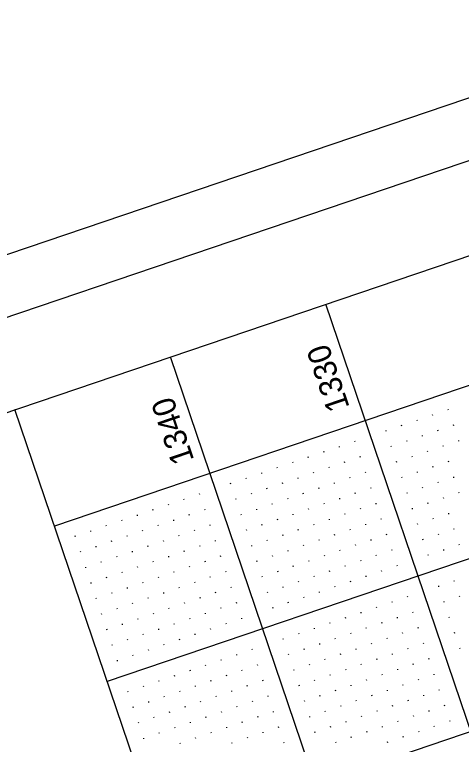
# Model space of a CAD drawing. Extents: x 2150318 to 2152065, y 143281 to 145371.
# Drawn here: x 2150900 to 2151036.1, y 145032.3 to 145254.7 of the extents above; entities that cross this region are included whole.
import ezdxf

# ---------------------------------------------------------------- set-up
doc = ezdxf.new("R2010")
doc.units = 0
for name, color, linetype in [('SHT_Plan_Profile_Sheet_Elev_Txt', 7, 'Continuous'), ('SHT_Plot_Shape_Full', 7, 'Continuous'), ('SHT_Plot_Shape_Half', 7, 'Continuous'), ('SHT_Profile_Grid_Major', 7, 'Continuous'), ('SHT_Profile_Grid_Minor', 7, 'Continuous'), ('SHT_Sheet_Border', 7, 'Continuous')]:
    doc.layers.add(name, color=color, linetype=linetype)

msp = doc.modelspace()

# ---------------------------------------------------------------- linework, layer by layer
at = {"layer": 'SHT_Plot_Shape_Full'}
msp.add_lwpolyline([(2150896.74, 143280.62), (2150318.46, 144985.2), (2151454.85, 145370.71), (2152033.12, 143666.13)], close=True, dxfattribs=at)
at = {"layer": 'SHT_Plot_Shape_Half'}
msp.add_lwpolyline([(2150909.49, 143371.4), (2150363.35, 144981.29), (2151405.04, 145334.68), (2151951.18, 143724.79)], close=True, dxfattribs=at)
at = {"layer": 'SHT_Profile_Grid_Major'}
for p, q in [((2151307.04, 145179.99), (2150928.24, 145051.49)), ((2151500.82, 143674.97), (2150994.83, 145166.47)), ((2151453.47, 143658.9), (2150947.48, 145150.41)), ((2151323.1, 145132.64), (2150944.3, 145004.14))]:
    msp.add_line(p, q, dxfattribs=at)
at = {"layer": 'SHT_Profile_Grid_Minor'}
for p, q in [((2151027.46, 145132.53), (2151027.38, 145132.77)), ((2151032.2, 145134.14), (2151032.12, 145134.38)), ((2151022.73, 145130.93), (2151022.65, 145131.16)), ((2151017.99, 145129.32), (2151017.91, 145129.56)), ((2151033.8, 145129.41), (2151033.72, 145129.64)), ((2151013.26, 145127.72), (2151013.18, 145127.95)), ((2151024.33, 145126.19), (2151024.25, 145126.43)), ((2151029.07, 145127.8), (2151028.99, 145128.04)), ((2151003.79, 145124.5), (2151003.71, 145124.74)), ((2151019.6, 145124.59), (2151019.52, 145124.82)), ((2151035.41, 145124.67), (2151035.33, 145124.91)), ((2150999.05, 145122.9), (2150998.97, 145123.13)), ((2151014.86, 145122.98), (2151014.78, 145123.22)), ((2151025.94, 145121.46), (2151025.86, 145121.69)), ((2151030.67, 145123.06), (2151030.59, 145123.3)), ((2150989.58, 145119.68), (2150989.5, 145119.92)), ((2150994.32, 145121.29), (2150994.24, 145121.53)), ((2151005.39, 145119.77), (2151005.31, 145120)), ((2151021.2, 145119.85), (2151021.12, 145120.09)), ((2150984.85, 145118.08), (2150984.77, 145118.31)), ((2151000.66, 145118.16), (2151000.58, 145118.4)), ((2151016.47, 145118.25), (2151016.39, 145118.48)), ((2151032.28, 145118.33), (2151032.2, 145118.57)), ((2150975.38, 145114.86), (2150975.3, 145115.1)), ((2150980.11, 145116.47), (2150980.03, 145116.71)), ((2150991.19, 145114.95), (2150991.11, 145115.19)), ((2150995.92, 145116.55), (2150995.84, 145116.79)), ((2151007, 145115.03), (2151006.92, 145115.27)), ((2151022.81, 145115.12), (2151022.73, 145115.35)), ((2151027.55, 145116.72), (2151027.47, 145116.96)), ((2150970.64, 145113.26), (2150970.56, 145113.49)), ((2150986.45, 145113.34), (2150986.37, 145113.58)), ((2151002.26, 145113.43), (2151002.18, 145113.66)), ((2151018.08, 145113.51), (2151018, 145113.75)), ((2151033.89, 145113.59), (2151033.81, 145113.83)), ((2150965.91, 145111.65), (2150965.83, 145111.89)), ((2150981.72, 145111.74), (2150981.64, 145111.97)), ((2150997.53, 145111.82), (2150997.45, 145112.06)), ((2151008.61, 145110.3), (2151008.53, 145110.53)), ((2151024.42, 145110.38), (2151024.34, 145110.62)), ((2151029.15, 145111.99), (2151029.07, 145112.22)), ((2150956.44, 145108.44), (2150956.36, 145108.68)), ((2150972.25, 145108.52), (2150972.17, 145108.76)), ((2150976.98, 145110.13), (2150976.9, 145110.37)), ((2150988.06, 145108.61), (2150987.98, 145108.84)), ((2150992.79, 145110.21), (2150992.71, 145110.45)), ((2151003.87, 145108.69), (2151003.79, 145108.93)), ((2151019.68, 145108.78), (2151019.6, 145109.01)), ((2151035.49, 145108.86), (2151035.41, 145109.1)), ((2150951.7, 145106.83), (2150951.62, 145107.07)), ((2150967.51, 145106.92), (2150967.43, 145107.15)), ((2150983.32, 145107), (2150983.24, 145107.24)), ((2150999.14, 145107.08), (2150999.06, 145107.32)), ((2151030.76, 145107.25), (2151030.68, 145107.49)), ((2150942.23, 145103.62), (2150942.15, 145103.86)), ((2150946.97, 145105.23), (2150946.89, 145105.46)), ((2150958.04, 145103.7), (2150957.96, 145103.94)), ((2150973.85, 145103.79), (2150973.77, 145104.03)), ((2150978.59, 145105.39), (2150978.51, 145105.63)), ((2150989.67, 145103.87), (2150989.59, 145104.11)), ((2150994.4, 145105.48), (2150994.32, 145105.72)), ((2151005.48, 145103.96), (2151005.4, 145104.19)), ((2151010.21, 145105.56), (2151010.13, 145105.8)), ((2151021.29, 145104.04), (2151021.21, 145104.28)), ((2151026.02, 145105.65), (2151025.94, 145105.88)), ((2150937.5, 145102.01), (2150937.42, 145102.25)), ((2150953.31, 145102.1), (2150953.23, 145102.33)), ((2150969.12, 145102.18), (2150969.04, 145102.42)), ((2150984.93, 145102.27), (2150984.85, 145102.5)), ((2151000.74, 145102.35), (2151000.66, 145102.59)), ((2151032.36, 145102.52), (2151032.28, 145102.75)), ((2150932.76, 145100.41), (2150932.68, 145100.64)), ((2150948.57, 145100.49), (2150948.49, 145100.73)), ((2150980.2, 145100.66), (2150980.12, 145100.9)), ((2150991.27, 145099.14), (2150991.19, 145099.37)), ((2150996.01, 145100.74), (2150995.93, 145100.98)), ((2151007.08, 145099.22), (2151007, 145099.46)), ((2151011.82, 145100.83), (2151011.74, 145101.06)), ((2151022.89, 145099.31), (2151022.81, 145099.54)), ((2151027.63, 145100.91), (2151027.55, 145101.15)), ((2150923.29, 145097.2), (2150923.21, 145097.43)), ((2150928.03, 145098.8), (2150927.95, 145099.04)), ((2150939.1, 145097.28), (2150939.02, 145097.52)), ((2150943.84, 145098.89), (2150943.76, 145099.12)), ((2150954.92, 145097.36), (2150954.83, 145097.6)), ((2150959.65, 145098.97), (2150959.57, 145099.21)), ((2150970.73, 145097.45), (2150970.65, 145097.68)), ((2150975.46, 145099.05), (2150975.38, 145099.29)), ((2150986.54, 145097.53), (2150986.46, 145097.77)), ((2151002.35, 145097.62), (2151002.27, 145097.85)), ((2151033.97, 145097.78), (2151033.89, 145098.02)), ((2150918.56, 145095.59), (2150918.48, 145095.83)), ((2150934.37, 145095.67), (2150934.29, 145095.91)), ((2150950.18, 145095.76), (2150950.1, 145095.99)), ((2150981.8, 145095.92), (2150981.72, 145096.16)), ((2150997.61, 145096.01), (2150997.53, 145096.25)), ((2151013.42, 145096.09), (2151013.34, 145096.33)), ((2151029.24, 145096.18), (2151029.16, 145096.41)), ((2150924.9, 145092.46), (2150924.82, 145092.7)), ((2150929.63, 145094.07), (2150929.55, 145094.3)), ((2150940.71, 145092.54), (2150940.63, 145092.78)), ((2150945.45, 145094.15), (2150945.36, 145094.39)), ((2150956.52, 145092.63), (2150956.44, 145092.86)), ((2150961.26, 145094.23), (2150961.18, 145094.47)), ((2150972.33, 145092.71), (2150972.25, 145092.95)), ((2150977.07, 145094.32), (2150976.99, 145094.56)), ((2150988.14, 145092.8), (2150988.06, 145093.03)), ((2150992.88, 145094.4), (2150992.8, 145094.64)), ((2151003.95, 145092.88), (2151003.87, 145093.12)), ((2151008.69, 145094.49), (2151008.61, 145094.72)), ((2151024.5, 145094.57), (2151024.42, 145094.81)), ((2151035.58, 145093.05), (2151035.5, 145093.28)), ((2150920.16, 145090.85), (2150920.08, 145091.09)), ((2150935.98, 145090.94), (2150935.9, 145091.17)), ((2150951.79, 145091.02), (2150951.71, 145091.26)), ((2150983.41, 145091.19), (2150983.33, 145091.43)), ((2150999.22, 145091.27), (2150999.14, 145091.51)), ((2151015.03, 145091.36), (2151014.95, 145091.59)), ((2151030.84, 145091.44), (2151030.76, 145091.68)), ((2150931.24, 145089.33), (2150931.16, 145089.57)), ((2150947.05, 145089.42), (2150946.97, 145089.65)), ((2150962.86, 145089.5), (2150962.78, 145089.74)), ((2150978.67, 145089.58), (2150978.59, 145089.82)), ((2150989.75, 145088.06), (2150989.67, 145088.3)), ((2150994.49, 145089.67), (2150994.4, 145089.9)), ((2151005.56, 145088.15), (2151005.48, 145088.38)), ((2151010.3, 145089.75), (2151010.22, 145089.99)), ((2151026.11, 145089.84), (2151026.03, 145090.07)), ((2150921.77, 145086.12), (2150921.69, 145086.36)), ((2150926.51, 145087.73), (2150926.43, 145087.96)), ((2150937.58, 145086.2), (2150937.5, 145086.44)), ((2150942.32, 145087.81), (2150942.24, 145088.05)), ((2150953.39, 145086.29), (2150953.31, 145086.52)), ((2150958.13, 145087.89), (2150958.05, 145088.13)), ((2150973.94, 145087.98), (2150973.86, 145088.21)), ((2150985.02, 145086.45), (2150984.93, 145086.69)), ((2151000.83, 145086.54), (2151000.75, 145086.78)), ((2151016.64, 145086.62), (2151016.56, 145086.86)), ((2150932.85, 145084.6), (2150932.77, 145084.83)), ((2150948.66, 145084.68), (2150948.58, 145084.92)), ((2150964.47, 145084.76), (2150964.39, 145085)), ((2150980.28, 145084.85), (2150980.2, 145085.09)), ((2150996.09, 145084.93), (2150996.01, 145085.17)), ((2151011.9, 145085.02), (2151011.82, 145085.25)), ((2150923.38, 145081.38), (2150923.3, 145081.62)), ((2150928.11, 145082.99), (2150928.03, 145083.23)), ((2150939.19, 145081.47), (2150939.11, 145081.7)), ((2150943.92, 145083.07), (2150943.84, 145083.31)), ((2150955, 145081.55), (2150954.92, 145081.79)), ((2150959.73, 145083.16), (2150959.65, 145083.39)), ((2150975.55, 145083.24), (2150975.46, 145083.48)), ((2150986.62, 145081.72), (2150986.54, 145081.96)), ((2150991.36, 145083.33), (2150991.28, 145083.56)), ((2151002.43, 145081.8), (2151002.35, 145082.04)), ((2151007.17, 145083.41), (2151007.09, 145083.65)), ((2151034.06, 145081.97), (2151033.97, 145082.21)), ((2150934.45, 145079.86), (2150934.37, 145080.1)), ((2150950.26, 145079.95), (2150950.18, 145080.18)), ((2150966.08, 145080.03), (2150965.99, 145080.27)), ((2150981.89, 145080.11), (2150981.81, 145080.35)), ((2150997.7, 145080.2), (2150997.62, 145080.43)), ((2151029.32, 145080.37), (2151029.24, 145080.6)), ((2150929.72, 145078.26), (2150929.64, 145078.49)), ((2150945.53, 145078.34), (2150945.45, 145078.58)), ((2150961.34, 145078.42), (2150961.26, 145078.66)), ((2150977.15, 145078.51), (2150977.07, 145078.74)), ((2150988.23, 145076.98), (2150988.15, 145077.22)), ((2150992.96, 145078.59), (2150992.88, 145078.83)), ((2151019.85, 145077.15), (2151019.77, 145077.39)), ((2151035.66, 145077.24), (2151035.58, 145077.47)), ((2150924.98, 145076.65), (2150924.9, 145076.89)), ((2150936.06, 145075.13), (2150935.98, 145075.36)), ((2150940.79, 145076.73), (2150940.71, 145076.97)), ((2150951.87, 145075.21), (2150951.79, 145075.45)), ((2150956.61, 145076.82), (2150956.53, 145077.05)), ((2150967.68, 145075.29), (2150967.6, 145075.53)), ((2150983.49, 145075.38), (2150983.41, 145075.62)), ((2151015.12, 145075.55), (2151015.03, 145075.78)), ((2151030.93, 145075.63), (2151030.85, 145075.87)), ((2150931.32, 145073.52), (2150931.24, 145073.76)), ((2150947.14, 145073.6), (2150947.06, 145073.84)), ((2150962.95, 145073.69), (2150962.87, 145073.93)), ((2150978.76, 145073.77), (2150978.68, 145074.01)), ((2151010.38, 145073.94), (2151010.3, 145074.18)), ((2150926.59, 145071.91), (2150926.51, 145072.15)), ((2150937.67, 145070.39), (2150937.59, 145070.63)), ((2150942.4, 145072), (2150942.32, 145072.23)), ((2150953.48, 145070.48), (2150953.4, 145070.71)), ((2150958.21, 145072.08), (2150958.13, 145072.32)), ((2150969.29, 145070.56), (2150969.21, 145070.8)), ((2151000.91, 145070.73), (2151000.83, 145070.96)), ((2151005.65, 145072.33), (2151005.56, 145072.57)), ((2151016.72, 145070.81), (2151016.64, 145071.05)), ((2151021.46, 145072.42), (2151021.38, 145072.65)), ((2151032.53, 145070.9), (2151032.45, 145071.13)), ((2150932.93, 145068.79), (2150932.85, 145069.02)), ((2150948.74, 145068.87), (2150948.66, 145069.11)), ((2150964.55, 145068.95), (2150964.47, 145069.19)), ((2150996.18, 145069.12), (2150996.1, 145069.36)), ((2151011.99, 145069.21), (2151011.91, 145069.44)), ((2150928.2, 145067.18), (2150928.12, 145067.42)), ((2150944.01, 145067.26), (2150943.93, 145067.5)), ((2150959.82, 145067.35), (2150959.74, 145067.58)), ((2150986.71, 145065.91), (2150986.63, 145066.15)), ((2150991.44, 145067.52), (2150991.36, 145067.75)), ((2151002.52, 145065.99), (2151002.44, 145066.23)), ((2151007.25, 145067.6), (2151007.17, 145067.84)), ((2151018.33, 145066.08), (2151018.25, 145066.31)), ((2151023.06, 145067.68), (2151022.98, 145067.92)), ((2151034.14, 145066.16), (2151034.06, 145066.4)), ((2150934.54, 145064.05), (2150934.46, 145064.29)), ((2150939.27, 145065.66), (2150939.19, 145065.89)), ((2150950.35, 145064.13), (2150950.27, 145064.37)), ((2150955.08, 145065.74), (2150955, 145065.98)), ((2150981.97, 145064.3), (2150981.89, 145064.54)), ((2150997.78, 145064.39), (2150997.7, 145064.62)), ((2151013.59, 145064.47), (2151013.51, 145064.71)), ((2150929.8, 145062.44), (2150929.72, 145062.68)), ((2150945.61, 145062.53), (2150945.53, 145062.76)), ((2150993.05, 145062.78), (2150992.97, 145063.02)), ((2151008.86, 145062.86), (2151008.78, 145063.1)), ((2151019.93, 145061.34), (2151019.85, 145061.58)), ((2151024.67, 145062.95), (2151024.59, 145063.18)), ((2151035.75, 145061.43), (2151035.66, 145061.66)), ((2150936.14, 145059.32), (2150936.06, 145059.55)), ((2150940.88, 145060.92), (2150940.8, 145061.16)), ((2150967.77, 145059.48), (2150967.69, 145059.72)), ((2150972.5, 145061.09), (2150972.42, 145061.33)), ((2150983.58, 145059.57), (2150983.5, 145059.8)), ((2150988.31, 145061.17), (2150988.23, 145061.41)), ((2150999.39, 145059.65), (2150999.31, 145059.89)), ((2151004.12, 145061.26), (2151004.04, 145061.49)), ((2151015.2, 145059.74), (2151015.12, 145059.97)), ((2150931.41, 145057.71), (2150931.33, 145057.95)), ((2150963.03, 145057.88), (2150962.95, 145058.11)), ((2150994.65, 145058.05), (2150994.57, 145058.28)), ((2151010.46, 145058.13), (2151010.38, 145058.37)), ((2151026.28, 145058.21), (2151026.2, 145058.45)), ((2150953.56, 145054.66), (2150953.48, 145054.9)), ((2150958.3, 145056.27), (2150958.22, 145056.51)), ((2150969.37, 145054.75), (2150969.29, 145054.99)), ((2150974.11, 145056.35), (2150974.03, 145056.59)), ((2150985.18, 145054.83), (2150985.1, 145055.07)), ((2150989.92, 145056.44), (2150989.84, 145056.68)), ((2151000.99, 145054.92), (2151000.91, 145055.15)), ((2151005.73, 145056.52), (2151005.65, 145056.76)), ((2151016.81, 145055), (2151016.73, 145055.24)), ((2151021.54, 145056.61), (2151021.46, 145056.84)), ((2150948.83, 145053.06), (2150948.75, 145053.29)), ((2150964.64, 145053.14), (2150964.56, 145053.38)), ((2150996.26, 145053.31), (2150996.18, 145053.55)), ((2151012.07, 145053.39), (2151011.99, 145053.63)), ((2151027.88, 145053.48), (2151027.8, 145053.71)), ((2150944.09, 145051.45), (2150944.01, 145051.69)), ((2150959.9, 145051.54), (2150959.82, 145051.77)), ((2150975.71, 145051.62), (2150975.63, 145051.86)), ((2150991.52, 145051.7), (2150991.44, 145051.94)), ((2151007.34, 145051.79), (2151007.26, 145052.02)), ((2151018.41, 145050.27), (2151018.33, 145050.5)), ((2151023.15, 145051.87), (2151023.07, 145052.11)), ((2150934.62, 145048.24), (2150934.54, 145048.48)), ((2150939.36, 145049.85), (2150939.28, 145050.08)), ((2150950.43, 145048.32), (2150950.35, 145048.56)), ((2150955.17, 145049.93), (2150955.09, 145050.17)), ((2150966.24, 145048.41), (2150966.16, 145048.64)), ((2150970.98, 145050.01), (2150970.9, 145050.25)), ((2150986.79, 145050.1), (2150986.71, 145050.33)), ((2150997.87, 145048.58), (2150997.79, 145048.81)), ((2151002.6, 145050.18), (2151002.52, 145050.42)), ((2151013.68, 145048.66), (2151013.6, 145048.9)), ((2151029.49, 145048.74), (2151029.41, 145048.98)), ((2150945.7, 145046.72), (2150945.62, 145046.95)), ((2150961.51, 145046.8), (2150961.43, 145047.04)), ((2150977.32, 145046.88), (2150977.24, 145047.12)), ((2150993.13, 145046.97), (2150993.05, 145047.21)), ((2151008.94, 145047.05), (2151008.86, 145047.29)), ((2151024.75, 145047.14), (2151024.67, 145047.37)), ((2150940.96, 145045.11), (2150940.88, 145045.35)), ((2150952.04, 145043.59), (2150951.96, 145043.83)), ((2150956.77, 145045.19), (2150956.69, 145045.43)), ((2150967.85, 145043.67), (2150967.77, 145043.91)), ((2150972.58, 145045.28), (2150972.5, 145045.52)), ((2150988.4, 145045.36), (2150988.32, 145045.6)), ((2150999.47, 145043.84), (2150999.39, 145044.08)), ((2151004.21, 145045.45), (2151004.13, 145045.68)), ((2151015.28, 145043.92), (2151015.2, 145044.16)), ((2151020.02, 145045.53), (2151019.94, 145045.77)), ((2151031.09, 145044.01), (2151031.01, 145044.25)), ((2150936.23, 145043.5), (2150936.15, 145043.74)), ((2150947.3, 145041.98), (2150947.22, 145042.22)), ((2150963.11, 145042.07), (2150963.03, 145042.3)), ((2150978.93, 145042.15), (2150978.85, 145042.39)), ((2150994.74, 145042.23), (2150994.66, 145042.47)), ((2151010.55, 145042.32), (2151010.47, 145042.55)), ((2151026.36, 145042.4), (2151026.28, 145042.64)), ((2150942.57, 145040.38), (2150942.49, 145040.61)), ((2150958.38, 145040.46), (2150958.3, 145040.7)), ((2150974.19, 145040.54), (2150974.11, 145040.78)), ((2150990, 145040.63), (2150989.92, 145040.86)), ((2151001.08, 145039.11), (2151001, 145039.34)), ((2151005.81, 145040.71), (2151005.73, 145040.95)), ((2151016.89, 145039.19), (2151016.81, 145039.43)), ((2151021.62, 145040.8), (2151021.54, 145041.03)), ((2151032.7, 145039.27), (2151032.62, 145039.51)), ((2150937.83, 145038.77), (2150937.75, 145039.01)), ((2150948.91, 145037.25), (2150948.83, 145037.48)), ((2150953.64, 145038.85), (2150953.56, 145039.09)), ((2150964.72, 145037.33), (2150964.64, 145037.57)), ((2150969.46, 145038.94), (2150969.38, 145039.17)), ((2150980.53, 145037.42), (2150980.45, 145037.65)), ((2150996.34, 145037.5), (2150996.26, 145037.74)), ((2151012.15, 145037.58), (2151012.07, 145037.82)), ((2151027.97, 145037.67), (2151027.89, 145037.9)), ((2150944.17, 145035.64), (2150944.09, 145035.88)), ((2150959.99, 145035.72), (2150959.91, 145035.96)), ((2150975.8, 145035.81), (2150975.72, 145036.05)), ((2150991.61, 145035.89), (2150991.53, 145036.13)), ((2151007.42, 145035.98), (2151007.34, 145036.21)), ((2151023.23, 145036.06), (2151023.15, 145036.3)), ((2150939.44, 145034.03), (2150939.36, 145034.27)), ((2150950.52, 145032.51), (2150950.44, 145032.75)), ((2150955.25, 145034.12), (2150955.17, 145034.36)), ((2150966.33, 145032.6), (2150966.25, 145032.83)), ((2150971.06, 145034.2), (2150970.98, 145034.44)), ((2150982.14, 145032.68), (2150982.06, 145032.92)), ((2150997.95, 145032.76), (2150997.87, 145033)), ((2151002.68, 145034.37), (2151002.6, 145034.61)), ((2151013.76, 145032.85), (2151013.68, 145033.08)), ((2151018.5, 145034.45), (2151018.42, 145034.69))]:
    msp.add_line(p, q, dxfattribs=at)
at = {"layer": 'SHT_Sheet_Border'}
for p, q in [((2151362, 145251.44), (2150912.18, 145098.84)), ((2151406.12, 143642.84), (2150900.13, 145134.35))]:
    msp.add_line(p, q, dxfattribs=at)
msp.add_lwpolyline([(2150901.85, 143471.77), (2150395.86, 144963.28), (2151390.2, 145300.6), (2151896.19, 143809.09)], close=True, dxfattribs=at)

# ---------------------------------------------------------------- texts
at = {"layer": 'SHT_Plan_Profile_Sheet_Elev_Txt'}
for s, p in [('1330', (2151002.15, 145135.06)), ('1340', (2150954.8, 145118.99))]:
    msp.add_text(s, height=7, rotation=108.7393, dxfattribs=at).set_placement(p)

doc.saveas('drawing.dxf')
